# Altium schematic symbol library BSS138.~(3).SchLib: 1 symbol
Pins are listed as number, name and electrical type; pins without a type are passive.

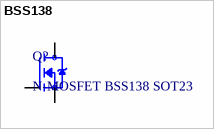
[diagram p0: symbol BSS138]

## BSS138
designator Q?, comment N-MOSFET BSS138 SOT23
N-Channel 50 V 220mA (Ta) 350mW (Ta) Surface Mount SOT-23-3; MF: onsemi
footprint N-MOSFET BSS138 SOT23 (N-MOSFET BSS138 SOT23 SOT95P240X111-3N)
pins: 1 G, 2 S, 3 D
